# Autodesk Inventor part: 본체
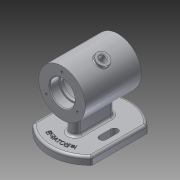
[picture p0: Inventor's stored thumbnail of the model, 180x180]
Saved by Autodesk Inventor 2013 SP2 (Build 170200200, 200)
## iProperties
Created: 2022-02
Part Number: 본체
Material: 알루미늄 6061
Document SubType Name: Modeling
Designer: i
Density: 2.71 g/cm^3
Mass: 497.101 g
Surface Area: 489.776 cm^2
Volume: 183.432 cm^3
Author: i
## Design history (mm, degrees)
sketch "스케치1"
  geometry: L1 (-36, 0)-(36, 0); L2 (-36, 0)-(-36, 30); L3 (-36, 30)-(36, 30); L4 (36, 30)-(36, 0); L5 (-36, 16)-(-24, 16); L6 (-24, 16)-(-24, 14); L7 (-24, 14)-(-20, 14); L8 (-20, 14)-(-20, 25); L9 (-20, 25)-(20, 25); L10 (20, 25)-(20, 14); L11 (20, 14)-(24, 14); L12 (24, 14)-(24, 16); L13 (24, 16)-(36, 16); 2 further points
  constraints: 26 end point, 7 perpendicular, 5 parallel, 2 point on line, 1 coincident, 1 horizontal, 1 midpoint
  dimensions: "d0" = 72 distance of L1.start L1.end; "d1" = 60 diameter of L3 L1; "d2" = 32 diameter of L5 L1; "d3" = 32 diameter of L13 L1; "d4" = 28 diameter of L7 L1; "d5" = 28 diameter of L11 L1; "d6" = 12 distance of L5.start L5.end; "d7" = 12 distance of L13.end L12.end; "d9" = 50 diameter of L9 L1; "d10" = 40 distance between parallel lines of L10 L8; "d11" = 4 distance between parallel lines of L6 L8
revolve "회전1" sketch "스케치1" stored, may be unused: angle "d12" = 90 deg
fillet "모깎기1" dims "d13" = 3
fillet "모깎기2" dims "d14" = 0.3
sketch "스케치2" dims "d15" = 46
  geometry: C1 r 16 at (0, 0) reference; 2 further points
  constraints: 2 vertical alignment, 1 coincident, 2 other
hole "구멍1" sketch "스케치2" at (0, 23) diameter "d16" = 3.242; stored, may be unused: countersink angle "d20" = 90 deg, drill point angle "d22" = 118 deg; dims "d17" = 8, "d18" = 4, "d19" = 2, "d21" = 10
sketch "스케치3"
  geometry: L1 (0, 0)-(28.579, 16.5); L2 (0, 0)-(33, 0); 1 further point
  constraints: 4 end point, 1 coincident, 1 equal length, 1 horizontal
  dimensions: "d28" = 33 distance of L1.start L1.end; "d29" = 30 deg angle of L2 L1
node "작업 평면1"
sketch "스케치4"
  geometry: C1 r 8 at (0, 0); 1 further point
  constraints: 1 centre point, 1 coincident
  dimensions: "d30" = 16 diameter of C1
extrude "돌출1" join sketch "스케치4" stored distance "d31" = 0; taper "d32" = 0 deg
sketch "스케치5"
  geometry: C1 r 8 at (0, 0) reference; C2 r 4 at (0, 0)
  constraints: 1 centre point, 1 coincident
  dimensions: "d33" = 8 diameter of C2
extrude "돌출2" cut sketch "스케치5" stored distance "d34" = 10; taper "d35" = 0 deg
fillet "모깎기3" dims "d36" = 1
fillet "모깎기4" dims "d37" = 1
node "작업 평면2"
sketch "스케치6"
  geometry: C1 r 52 at (0, 0); 1 further point
  constraints: 1 centre point, 1 coincident
  dimensions: "d39" = 104 diameter of C1
extrude "돌출3" join sketch "스케치6" distance "d40" = 10; taper "d41" = 0 deg
sketch "스케치7"
  geometry: L1 (-52, 38)-(52, 38); L2 (52, 38)-(52, -38); L3 (52, -38)-(-52, -38); L4 (-52, -38)-(-52, 38); L5 (-52, 38)-(52, -38); L6 (52, 38)-(-52, -38); L7 (-52, -38)-(52, -38); L8 (52, -38)-(52, -52); L9 (52, -52)-(-52, -52); L10 (-52, -52)-(-52, -38); A1 r 52 centre (0, 0) between (-52, 0) and (0, -52) reference; 1 further point
  constraints: 20 end point, 5 midpoint, 4 parallel, 2 horizontal, 2 perpendicular, 2 point on circle, 1 vertical alignment
  dimensions: "d42" = 76 distance of L1.end L2.end
extrude "돌출4" cut sketch "스케치7" stored distance "d43" = 10; taper "d44" = 0 deg
sketch "스케치8"
  geometry: L1 (-19, 7)-(19, 7); L2 (19, 7)-(19, -7); L3 (19, -7)-(-19, -7); L4 (-19, -7)-(-19, 7); L5 (-19, 7)-(19, -7); L6 (19, 7)-(-19, -7); A1 r 52 centre (0, 0) between (35.496, -38) and (35.496, 38) reference; A2 r 7 centre (-19, 0) between (-19, 7) and (-19, -7); A3 r 7 centre (19, 0) between (19, -7) and (19, 7)
  constraints: 12 end point, 4 midpoint, 4 point on circle, 2 centre point, 2 parallel, 1 horizontal, 1 perpendicular
  dimensions: "d45" = 38 distance of L2.end L3.end; "d46" = 14 distance of L1.end L2.end
extrude "돌출5" join sketch "스케치8" stored distance "d47" = 10; taper "d48" = 0 deg
sketch "스케치9"
  geometry: L1 (-7.5, 28.5)-(7.5, 28.5); L2 (7.5, 28.5)-(7.5, 19.5); L3 (7.5, 19.5)-(-7.5, 19.5); L4 (-7.5, 19.5)-(-7.5, 28.5); L5 (-7.5, 28.5)-(7.5, 19.5); L6 (7.5, 28.5)-(-7.5, 19.5); A1 r 52 centre (0, 0) between (-35.496, 38) and (-35.496, -38) reference; A2 r 4.5 centre (-7.5, 24) between (-7.5, 28.5) and (-7.5, 19.5); A3 r 4.5 centre (7.5, 24) between (7.5, 19.5) and (7.5, 28.5); 2 further points
  constraints: 12 end point, 5 midpoint, 4 point on circle, 2 centre point, 2 parallel, 1 horizontal, 1 perpendicular, 1 vertical alignment
  dimensions: "d49" = 15 distance of L2.end L3.end; "d50" = 9 distance of L1.end L2.end; "d51" = 24 distance of point (0, 24) A1.centre
extrude "돌출6" cut sketch "스케치9" stored distance "d52" = 10; taper "d53" = 0 deg
sketch "스케치10"
  geometry: C1 r 42.5 at (0, 0); A1 r 52 centre (0, 0) between (35.496, -38) and (35.496, 38) reference
  constraints: 1 centre point, 1 coincident, 1 other
  dimensions: "d54" = 85 diameter of C1
feature "엠보싱1" sketch "스케치10" dims "d0" = 72, "d1" = 60, "d2" = 32, "d3" = 32, "d4" = 28, "d5" = 28, "d6" = 12, "d7" = 12, "d9" = 50, "d10" = 40, "d11" = 4, "d14" = 0.3, "d56" = 0.5, "d57" = 0
chamfer "모따기1" distance "d58" = 1; stored, may be unused: second distance "d59" = 2, angle "d60" = 45 deg
fillet "모깎기5" dims "d61" = 3
fillet "모깎기6" dims "d62" = 3
fillet "모깎기7" dims "d63" = 3
node "솔리드1"
pattern_circular "원형 패턴1" dims angle "d24" = 360 deg
mirror "대칭1"
mirror "대칭2"
mirror "대칭3"
other parameters: "d38" = -62
